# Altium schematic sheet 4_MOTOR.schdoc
size 307 x 218 mm; Symbol: Sheet-Symbol_A4; Device: Sheet-Symbol_A4; @Project Name: Hexapod; @Page Count: 5; @Update Date: 2024-12-17; @Create Date: 2024-10-16; @Schematic Name: Schematic1; @Page No: 4; @Page Name: MOTOR; Company: EasyEDA.com; Version: V1.0; Page Size: A4; @Create Time: 14:29:40; @Update Time: 14:10:32; Title Block Position: 3; Width: 1170; Height: 825; Region Start: 1; X Region Count: 6; Y Region Count: 4; Blade Width: 10; @Board Name: Hexapod
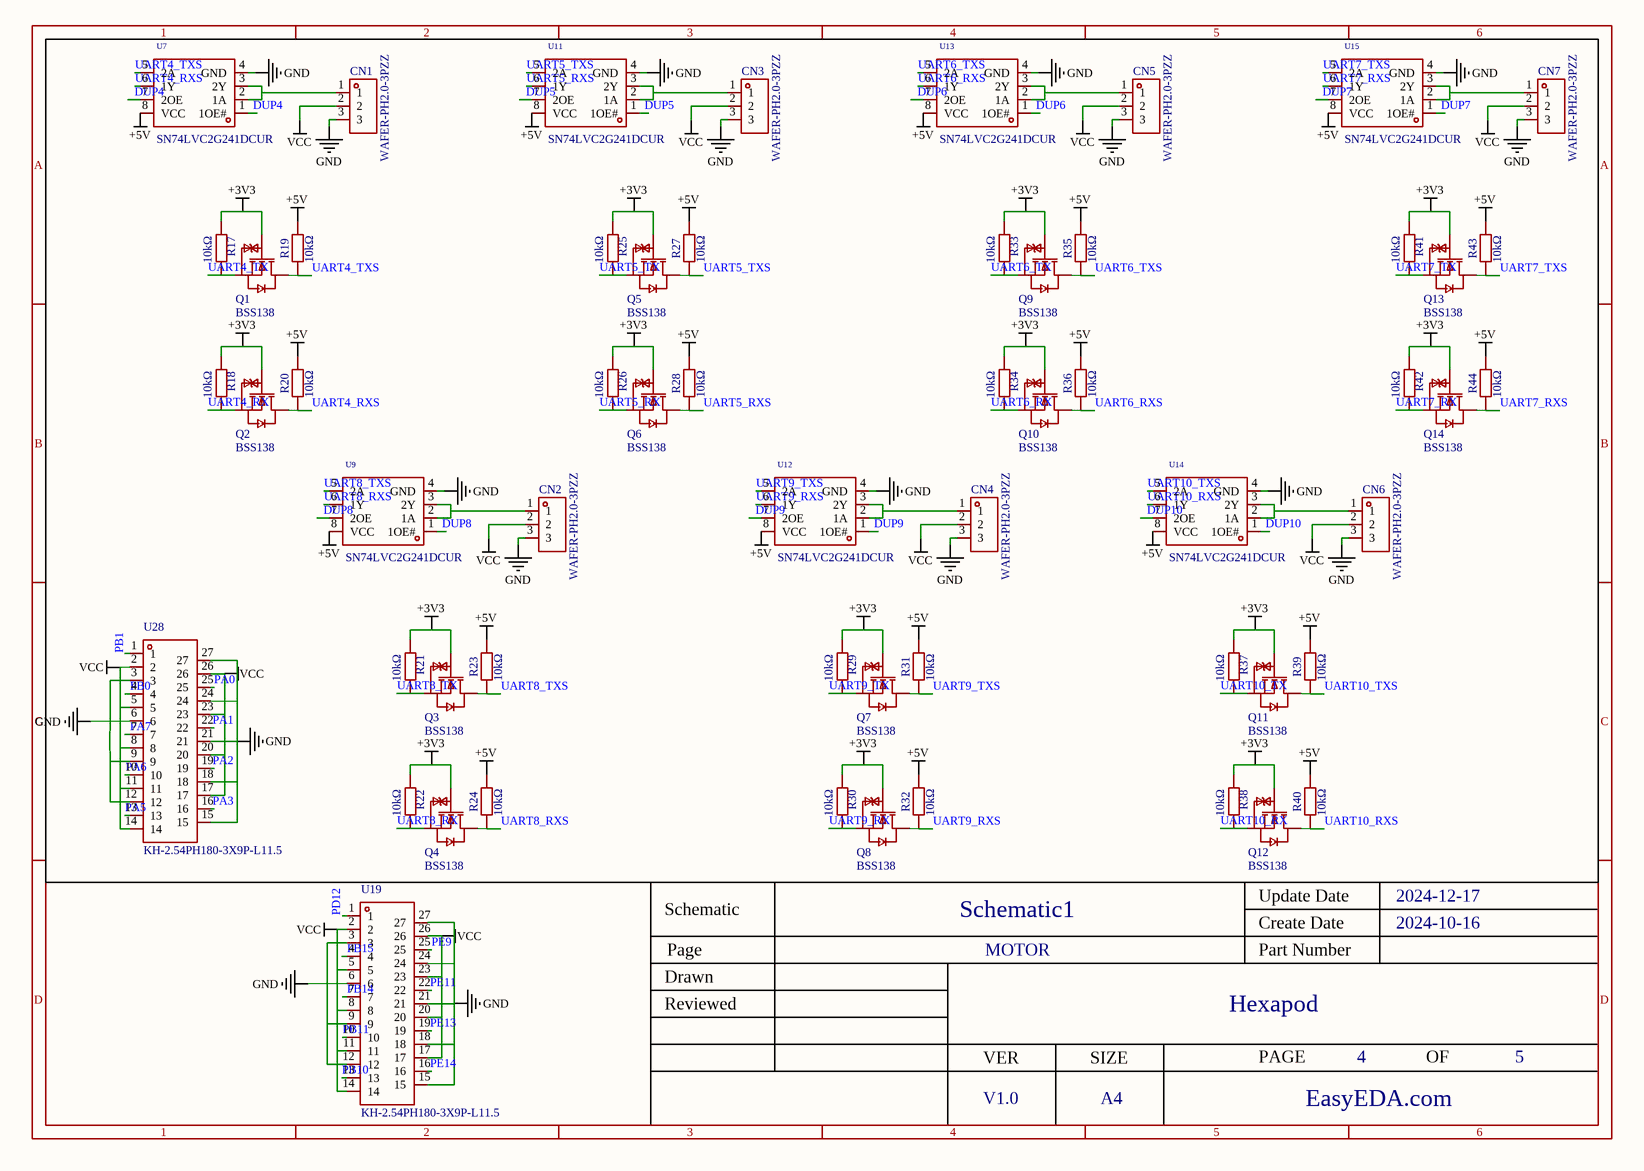
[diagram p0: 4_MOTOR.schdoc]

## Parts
CN1  WAFER-PH2.0-3PZZ  [CONN-TH_PH2.0D-L-3P]
CN2  WAFER-PH2.0-3PZZ  [CONN-TH_PH2.0D-L-3P]
CN3  WAFER-PH2.0-3PZZ  [CONN-TH_PH2.0D-L-3P]
CN4  WAFER-PH2.0-3PZZ  [CONN-TH_PH2.0D-L-3P]
CN5  WAFER-PH2.0-3PZZ  [CONN-TH_PH2.0D-L-3P]
CN6  WAFER-PH2.0-3PZZ  [CONN-TH_PH2.0D-L-3P]
CN7  WAFER-PH2.0-3PZZ  [CONN-TH_PH2.0D-L-3P]
Q1  BSS138  [SOT-23-3_L2.9-W1.3-P1.90-LS2.4-BR]
Q2  BSS138  [SOT-23-3_L2.9-W1.3-P1.90-LS2.4-BR]
Q3  BSS138  [SOT-23-3_L2.9-W1.3-P1.90-LS2.4-BR]
Q4  BSS138  [SOT-23-3_L2.9-W1.3-P1.90-LS2.4-BR]
Q5  BSS138  [SOT-23-3_L2.9-W1.3-P1.90-LS2.4-BR]
Q6  BSS138  [SOT-23-3_L2.9-W1.3-P1.90-LS2.4-BR]
Q7  BSS138  [SOT-23-3_L2.9-W1.3-P1.90-LS2.4-BR]
Q8  BSS138  [SOT-23-3_L2.9-W1.3-P1.90-LS2.4-BR]
Q9  BSS138  [SOT-23-3_L2.9-W1.3-P1.90-LS2.4-BR]
Q10  BSS138  [SOT-23-3_L2.9-W1.3-P1.90-LS2.4-BR]
Q11  BSS138  [SOT-23-3_L2.9-W1.3-P1.90-LS2.4-BR]
Q12  BSS138  [SOT-23-3_L2.9-W1.3-P1.90-LS2.4-BR]
Q13  BSS138  [SOT-23-3_L2.9-W1.3-P1.90-LS2.4-BR]
Q14  BSS138  [SOT-23-3_L2.9-W1.3-P1.90-LS2.4-BR]
R17  10kΩ  [R0402]
R18  10kΩ  [R0402]
R19  10kΩ  [R0402]
R20  10kΩ  [R0402]
R21  10kΩ  [R0402]
R22  10kΩ  [R0402]
R23  10kΩ  [R0402]
R24  10kΩ  [R0402]
R25  10kΩ  [R0402]
R26  10kΩ  [R0402]
R27  10kΩ  [R0402]
R28  10kΩ  [R0402]
R29  10kΩ  [R0402]
R30  10kΩ  [R0402]
R31  10kΩ  [R0402]
R32  10kΩ  [R0402]
R33  10kΩ  [R0402]
R34  10kΩ  [R0402]
R35  10kΩ  [R0402]
R36  10kΩ  [R0402]
R37  10kΩ  [R0402]
R38  10kΩ  [R0402]
R39  10kΩ  [R0402]
R40  10kΩ  [R0402]
R41  10kΩ  [R0402]
R42  10kΩ  [R0402]
R43  10kΩ  [R0402]
R44  10kΩ  [R0402]
U7  SN74LVC2G241DCUR  [VSSOP-8_L2.3-W2.0-P0.50-LS3.1-BR]
U9  SN74LVC2G241DCUR  [VSSOP-8_L2.3-W2.0-P0.50-LS3.1-BR]
U11  SN74LVC2G241DCUR  [VSSOP-8_L2.3-W2.0-P0.50-LS3.1-BR]
U12  SN74LVC2G241DCUR  [VSSOP-8_L2.3-W2.0-P0.50-LS3.1-BR]
U13  SN74LVC2G241DCUR  [VSSOP-8_L2.3-W2.0-P0.50-LS3.1-BR]
U14  SN74LVC2G241DCUR  [VSSOP-8_L2.3-W2.0-P0.50-LS3.1-BR]
U15  SN74LVC2G241DCUR  [VSSOP-8_L2.3-W2.0-P0.50-LS3.1-BR]
U19  KH-2.54PH180-3X9P-L11.5  [HDR-TH_27P-P2.54-V-M-R3-C9-S5.08]
U28  KH-2.54PH180-3X9P-L11.5  [HDR-TH_27P-P2.54-V-M-R3-C9-S5.08]

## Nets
+3V3: Q1.1(G) Q2.1(G) Q3.1(G) Q4.1(G) Q5.1(G) Q6.1(G) Q7.1(G) Q8.1(G) Q9.1(G) Q10.1(G) Q11.1(G) Q12.1(G) Q13.1(G) Q14.1(G) R17.2 R18.2 R21.2 R22.2 R25.2 R26.2 R29.2 R30.2 R33.2 R34.2 R37.2 R38.2 R41.2 R42.2
+5V: R19.2 R20.2 R23.2 R24.2 R27.2 R28.2 R31.2 R32.2 R35.2 R36.2 R39.2 R40.2 R43.2 R44.2 U7.8(VCC) U9.8(VCC) U11.8(VCC) U12.8(VCC) U13.8(VCC) U14.8(VCC) U15.8(VCC)
GND: CN1.3 CN2.3 CN3.3 CN4.3 CN5.3 CN6.3 CN7.3 U7.4(GND) U9.4(GND) U11.4(GND) U12.4(GND) U13.4(GND) U14.4(GND) U15.4(GND) U19.3 U19.6 U19.9 U19.12 U19.15 U19.18 U19.21 U19.24 U19.27 U28.3 U28.6 U28.9 U28.12 U28.15 U28.18 U28.21 U28.24 U28.27
VCC: CN1.2 CN2.2 CN3.2 CN4.2 CN5.2 CN6.2 CN7.2 U19.2 U19.5 U19.8 U19.11 U19.14 U19.17 U19.20 U19.23 U19.26 U28.2 U28.5 U28.8 U28.11 U28.14 U28.17 U28.20 U28.23 U28.26
DUP4: U7.1(1OE#) U7.7(2OE)
DUP5: U11.1(1OE#) U11.7(2OE)
DUP6: U13.1(1OE#) U13.7(2OE)
DUP7: U15.1(1OE#) U15.7(2OE)
DUP8: U9.1(1OE#) U9.7(2OE)
DUP9: U12.1(1OE#) U12.7(2OE)
DUP10: U14.1(1OE#) U14.7(2OE)
PA0: U28.25
PA1: U28.22
PA2: U28.19
PA3: U28.16
PA5: U28.13
PA6: U28.10
PA7: U28.7
PB0: U28.4
PB1: U28.1
PB10: U19.13
PB11: U19.10
PB14: U19.7
PB15: U19.4
PD12: U19.1
PE9: U19.25
PE11: U19.22
PE13: U19.19
PE14: U19.16
UART4_RX: Q2.2(S) R18.1
UART4_RXS: Q2.3(D) R20.1 U7.6(1Y)
UART4_TX: Q1.2(S) R17.1
UART4_TXS: Q1.3(D) R19.1 U7.5(2A)
UART5_RX: Q6.2(S) R26.1
UART5_RXS: Q6.3(D) R28.1 U11.6(1Y)
UART5_TX: Q5.2(S) R25.1
UART5_TXS: Q5.3(D) R27.1 U11.5(2A)
UART6_RX: Q10.2(S) R34.1
UART6_RXS: Q10.3(D) R36.1 U13.6(1Y)
UART6_TX: Q9.2(S) R33.1
UART6_TXS: Q9.3(D) R35.1 U13.5(2A)
UART7_RX: Q14.2(S) R42.1
UART7_RXS: Q14.3(D) R44.1 U15.6(1Y)
UART7_TX: Q13.2(S) R41.1
UART7_TXS: Q13.3(D) R43.1 U15.5(2A)
UART8_RX: Q4.2(S) R22.1
UART8_RXS: Q4.3(D) R24.1 U9.6(1Y)
UART8_TX: Q3.2(S) R21.1
UART8_TXS: Q3.3(D) R23.1 U9.5(2A)
UART9_RX: Q8.2(S) R30.1
UART9_RXS: Q8.3(D) R32.1 U12.6(1Y)
UART9_TX: Q7.2(S) R29.1
UART9_TXS: Q7.3(D) R31.1 U12.5(2A)
UART10_RX: Q12.2(S) R38.1
UART10_RXS: Q12.3(D) R40.1 U14.6(1Y)
UART10_TX: Q11.2(S) R37.1
UART10_TXS: Q11.3(D) R39.1 U14.5(2A)
NetCN1_1: CN1.1 U7.2(1A) U7.3(2Y)
NetCN2_1: CN2.1 U9.2(1A) U9.3(2Y)
NetCN3_1: CN3.1 U11.2(1A) U11.3(2Y)
NetCN4_1: CN4.1 U12.2(1A) U12.3(2Y)
NetCN5_1: CN5.1 U13.2(1A) U13.3(2Y)
NetCN6_1: CN6.1 U14.2(1A) U14.3(2Y)
NetCN7_1: CN7.1 U15.2(1A) U15.3(2Y)

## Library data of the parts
CN1-CN7 = WAFER-PH2.0-3PZZ: Manufacturer: XUNPU(讯普); Add into BOM: yes; Pins Structure: 1x3P; Pitch: 2mm; Reference Series: PH; Number of PINs Per Row: 3; Current Rating (Max): 2A
Q1-Q14 = BSS138_C5224260: Manufacturer: ElecSuper(静芯微); Add into BOM: yes; Type: 1 N-Channel; Drain Source Voltage (Vdss): 60V; Continuous Drain Current (Id): 300mA; Drain Source On Resistance (RDS(on)@Vgs,Id): 1.8Ω@10V; Power Dissipation (Pd): 350mW; Gate Threshold Voltage (Vgs(th)@Id): 1.1V@250uA; Total Gate Charge (Qg@Vgs): 1.6nC@4.5V; Input Capacitance (Ciss@Vds): 15pF@0V; Reverse Transfer Capacitance (Crss@Vds): 1.3pF@25V
R17-R44 = RC0402FR-0710KL: Manufacturer: YAGEO(国巨); Add into BOM: yes; Tolerance: ±1%; Temperature Coefficient: ±100ppm/℃
U7 U9 U11-U15 = SN74LVC2G241DCUR: Manufacturer: TI(德州仪器); Add into BOM: yes
U19 U28 = KH-2.54PH180-3X9P-L11.5: Manufacturer: kinghelm(金航标); Add into BOM: yes; Pin Structure: 3x9P; Pitch: 2.54mm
